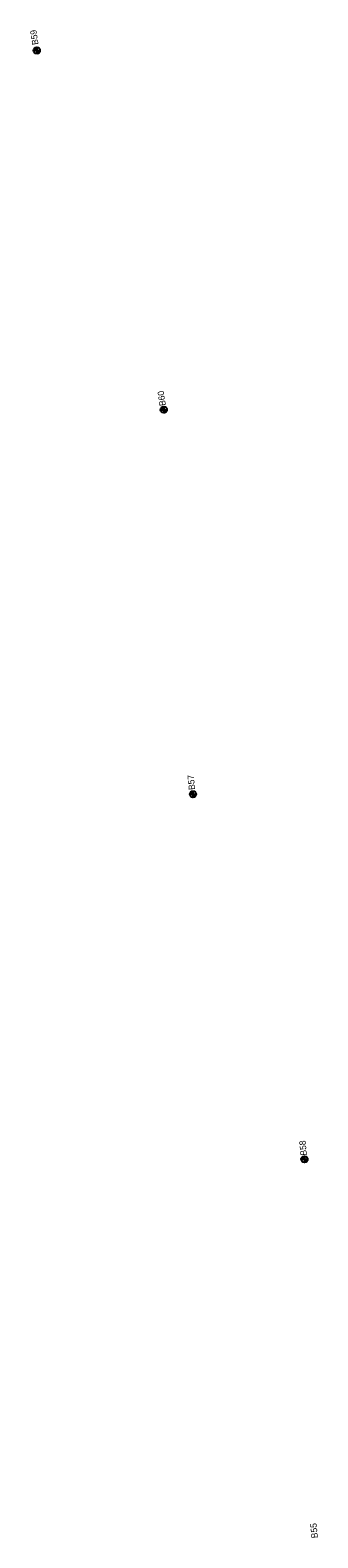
# Model space of a CAD drawing. Extents: x 327762 to 372792, y 127949 to 259367.
# Drawn here: x 359686 to 360141, y 160534 to 162912 of the extents above; entities that cross this region are included whole.
import ezdxf

# ---------------------------------------------------------------- set-up
doc = ezdxf.new("R2010")
doc.units = 0
for name, color, linetype in [('E_SOIL_BORE1 [KAPUR_CADDS_LEVELS]', 7, 'Continuous'), ('E_SOIL_BORE2 [KAPUR_CADDS_LEVELS]', 7, 'Continuous'), ('P_MARK', 7, 'Continuous')]:
    doc.layers.add(name, color=color, linetype=linetype)

msp = doc.modelspace()

# ---------------------------------------------------------------- linework, layer by layer
at = {"layer": 'P_MARK'}
for p, q in [((359692, 162879.9), (359702, 162879.9)), ((359697, 162884.9), (359697, 162874.9)), ((359892.4, 162313.3), (359902.4, 162313.3)), ((359897.4, 162318.3), (359897.4, 162308.3)), ((359938.5, 161706.9), (359948.5, 161706.9)), ((359943.5, 161711.9), (359943.5, 161701.9)), ((360119.5, 161136), (360119.5, 161126)), ((360114.5, 161131), (360124.5, 161131))]:
    msp.add_line(p, q, dxfattribs=at)
for centre in [(359697, 162879.9), (359897.4, 162313.3), (359943.5, 161706.9), (360119.5, 161131)]:
    msp.add_circle(centre, 5, dxfattribs=at)
for centre, radius, start, end in [((359697, 162879.9), 4.5, 89.9869, 179.9869), ((359697, 162879.9), 4, 89.9869, 179.9869), ((359697, 162879.9), 3.5, 89.9869, 179.9869), ((359697, 162879.9), 3, 89.9869, 179.9869), ((359697, 162879.9), 2.5, 89.9869, 179.9869), ((359697, 162879.9), 2, 89.9869, 179.9869), ((359697, 162879.9), 1.5, 89.9869, 179.9869), ((359697, 162879.9), 1, 89.9869, 179.9869), ((359697, 162879.9), 0.5, 89.9869, 179.9869), ((359697, 162879.9), 4.5, 269.9869, 359.9869), ((359697, 162879.9), 4, 269.9869, 359.9869), ((359697, 162879.9), 3.5, 269.9869, 359.9869), ((359697, 162879.9), 3, 269.9869, 359.9869), ((359697, 162879.9), 2.5, 269.9869, 359.9869), ((359697, 162879.9), 2, 269.9869, 359.9869), ((359697, 162879.9), 1.5, 269.9869, 359.9869), ((359697, 162879.9), 1, 269.9869, 359.9869), ((359697, 162879.9), 0.5, 269.9869, 359.9869), ((359897.4, 162313.3), 4.5, 89.9869, 179.9869), ((359897.4, 162313.3), 4, 89.9869, 179.9869), ((359897.4, 162313.3), 3.5, 89.9869, 179.9869), ((359897.4, 162313.3), 3, 89.9869, 179.9869), ((359897.4, 162313.3), 2.5, 89.9869, 179.9869), ((359897.4, 162313.3), 2, 89.9869, 179.9869), ((359897.4, 162313.3), 1.5, 89.9869, 179.9869), ((359897.4, 162313.3), 1, 89.9869, 179.9869), ((359897.4, 162313.3), 0.5, 89.9869, 179.9869), ((359897.4, 162313.3), 4.5, 269.9869, 359.9869), ((359897.4, 162313.3), 4, 269.9869, 359.9869), ((359897.4, 162313.3), 3.5, 269.9869, 359.9869), ((359897.4, 162313.3), 3, 269.9869, 359.9869), ((359897.4, 162313.3), 2.5, 269.9869, 359.9869), ((359897.4, 162313.3), 2, 269.9869, 359.9869), ((359897.4, 162313.3), 1.5, 269.9869, 359.9869), ((359897.4, 162313.3), 1, 269.9869, 359.9869), ((359897.4, 162313.3), 0.5, 269.9869, 359.9869), ((359943.5, 161706.9), 4.5, 89.9869, 179.9869), ((359943.5, 161706.9), 4, 89.9869, 179.9869), ((359943.5, 161706.9), 3.5, 89.9869, 179.9869), ((359943.5, 161706.9), 3, 89.9869, 179.9869), ((359943.5, 161706.9), 2.5, 89.9869, 179.9869), ((359943.5, 161706.9), 2, 89.9869, 179.9869), ((359943.5, 161706.9), 1.5, 89.9869, 179.9869), ((359943.5, 161706.9), 1, 89.9869, 179.9869), ((359943.5, 161706.9), 0.5, 89.9869, 179.9869), ((359943.5, 161706.9), 4.5, 269.9869, 359.9869), ((359943.5, 161706.9), 4, 269.9869, 359.9869), ((359943.5, 161706.9), 3.5, 269.9869, 359.9869), ((359943.5, 161706.9), 3, 269.9869, 359.9869), ((359943.5, 161706.9), 2.5, 269.9869, 359.9869), ((359943.5, 161706.9), 2, 269.9869, 359.9869), ((359943.5, 161706.9), 1.5, 269.9869, 359.9869), ((359943.5, 161706.9), 1, 269.9869, 359.9869), ((359943.5, 161706.9), 0.5, 269.9869, 359.9869), ((360119.5, 161131), 4.5, 89.9869, 179.9869), ((360119.5, 161131), 4, 89.9869, 179.9869), ((360119.5, 161131), 3.5, 89.9869, 179.9869), ((360119.5, 161131), 3, 89.9869, 179.9869), ((360119.5, 161131), 2.5, 89.9869, 179.9869), ((360119.5, 161131), 2, 89.9869, 179.9869), ((360119.5, 161131), 1.5, 89.9869, 179.9869), ((360119.5, 161131), 1, 89.9869, 179.9869), ((360119.5, 161131), 0.5, 89.9869, 179.9869), ((360119.5, 161131), 4.5, 269.9869, 359.9869), ((360119.5, 161131), 4, 269.9869, 359.9869), ((360119.5, 161131), 3.5, 269.9869, 359.9869), ((360119.5, 161131), 3, 269.9869, 359.9869), ((360119.5, 161131), 2.5, 269.9869, 359.9869), ((360119.5, 161131), 2, 269.9869, 359.9869), ((360119.5, 161131), 1.5, 269.9869, 359.9869), ((360119.5, 161131), 1, 269.9869, 359.9869), ((360119.5, 161131), 0.5, 269.9869, 359.9869)]:
    msp.add_arc(centre, radius, start, end, dxfattribs=at)

# ---------------------------------------------------------------- texts
at = {"layer": 'E_SOIL_BORE1 [KAPUR_CADDS_LEVELS]'}
for s, rotation, p in [('B60', 98.5151, (359900.8, 162320.1)), ('B57', 95.5802, (359947, 161714.1))]:
    msp.add_text(s, height=10, rotation=rotation, dxfattribs=at).set_placement(p)
at = {"layer": 'E_SOIL_BORE2 [KAPUR_CADDS_LEVELS]'}
for s, rotation, p in [('B59', 98.5151, (359699.7, 162889.5)), ('B58', 95.5802, (360123.4, 161137.4)), ('B55', 95.5802, (360140.7, 160533.9))]:
    msp.add_text(s, height=10, rotation=rotation, dxfattribs=at).set_placement(p)

doc.saveas('drawing.dxf')
